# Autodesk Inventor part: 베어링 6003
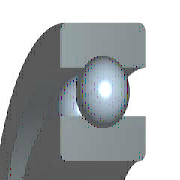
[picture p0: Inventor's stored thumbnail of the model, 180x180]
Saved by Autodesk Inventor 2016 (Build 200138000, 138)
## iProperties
Created: 2012-02
Part Number: 베어링 6003
Material: 강철, 연강
Description: 깊은 그루브 볼 베어링
Document SubType Name: Modeling
Standard: KS B 2023
Designer: mduedu
Standards Organization: KS
Language: ko-KR
Size Designation: 6003 - 17 x 35 x 10
Categories: <MemberInstance><Categories><Category DisplayName="샤프트 부품" InternalName="7f7aeb1f-a693-4053-b835-cee3144e0d98" Mnemonic="SHFT"><Category DisplayName="베어링" Inter
Density: 1 g/cm^3
Appearance: 강철
IsCustomPart: 1
Author: mduedu
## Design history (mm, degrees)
sketch "스케치" dims "d0" = 4.68 (= -0.26 x WD + 0.26 x BD)
  geometry: L1 (2.66, 13)-(7.34, 13); L2 (5, 13)-(5, 10.66); L3 (5, 13)-(5, 15.34); L4 (3.261, 11.434)-(0, 11.434); L5 (0, 8.5)-(10, 8.5); L6 (3.261, 14.566)-(0, 14.566); L7 (0, 17.5)-(10, 17.5); L8 (10, 8.5)-(10, 11.434); L9 (6.739, 11.434)-(10, 11.434); L10 (6.739, 14.566)-(10, 14.566); L11 (10, 17.5)-(10, 14.566); L12 (-1.4, 0)-(8.4, 0) reference; L13 (0, -0.3)-(0, 5.3) reference
  constraints: 22 end point, 4 point on line, 2 collinear, 2 perpendicular, 2 symmetric about line, 1 midpoint, 1 parallel, 14 other
  dimensions: "d9" = 17 diameter of L5 L12 (= WD); "d11" = 35 diameter of L7 L12 (= BD); "d12" = 10 distance between parallel lines of L8 L13 (= KB); "d13" = 22.868 diameter of L9 L12 (= 0.326 x BD + 0.674 x WD)
revolve "본체" stored, may be unused: angle "d6" = 90 deg
revolve "볼" stored, may be unused: angle "d7" = 90 deg
pattern_circular "IDS_ARRAYBALL[SIMPL:T]" dims angle "d3" = 360 deg
body "Solid1"
fillet "모깎기1" dims "d1" = 0.3 (= KRS)
other parameters: "WD" = 17 [user parameter; used in 5 equation terms], "BD" = 35 [user parameter; used in 5 equation terms], "KB" = 10 [user parameter; used in 1 equation term], "KRS" = 0.3 [user parameter; used in 1 equation term], "d4" = 0, "d5" = 0, "d8" = 0, "d14" = 0, "d15" = 0, "BBA" = 0 [user parameter], "BC0" = 3250000 [user parameter], "BC" = 6050000 [user parameter], "BR" = 17.5 (= 0.5 x BD) [user parameter], "WR" = 8.5 (= 0.5 x WD) [user parameter]
